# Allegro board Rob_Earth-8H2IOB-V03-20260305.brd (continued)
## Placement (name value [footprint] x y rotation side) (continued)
TVS3616  ESD54231N-2/TR  [ESD0402H0_55-ESD54231]  186.1 7.96 270 top
TVS3617  ESD54231N-2/TR  [ESD0402H0_55-ESD54231]  188.64 7.94 270 top
TVS3900  ESD54231N-2/TR  [ESD0402H0_55-ESD54231]  128.54 111.52 270 top
TVS3901  ESD54231N-2/TR  [ESD0402H0_55-ESD54231]  128.54 109.57 90 top
U500  LM5143QRWGRQ1  [QFN40-0_5-6X6H0_8-LM5143]  91.51 72.71 270 bottom
U501  LM5060Q1MM/NOPB  [VSSOP10-0_5-3X5H1_1-IM5060]  130.12 15.27 90 bottom
U504  74LVC1T45XC6G/TR  [SC70-6-0_65-2X1_25H1_1]  127.98 22.21 270 bottom
U506  SGM431VAXN3LG/TR  [SOT23H1_2]  123.05 14.07 270 bottom
U600  MAX25207ATPA/VY+  [QFN20-0_5-4X4H0_8]  69.79 54.01 90 bottom
U700  LM5177DCPR  [TSSOP38-0_5-9_8X4_5H1_2]  102.13 29.95 180 bottom
U800  SGM6613AYTQX13GTR  [QFN13-0_5-3X3_5H0_8-SGM6613A]  120.96 6.37 270 bottom
U802  SGM61030BXTEP7G/TR  [DFN7-0_5-SQ2H0_8-SGM61030]  54.9 40.69 90 bottom
U804  SGM2590DXN5G/TR  [SOT23-5H1_45]  50.91 57.1 90 bottom
U805  SGM2590DXN5G/TR  [SOT23-5H1_45]  50.93 52.47 90 bottom
U806  SGM61030BXTEP7G/TR  [DFN7-0_5-SQ2H0_8-SGM61030]  55.39 112.4 180 bottom
U807  SGM61030BXTEP7G/TR  [DFN7-0_5-SQ2H0_8-SGM61030]  139.54 89.39 0 top
U808  SGM2590DXN5G/TR  [SOT23-5H1_45]  139.48 94.14 180 top
U900  IT6563FN/DW(EW1)  [QFN56-0_4-7X7H0_9-IT6563]  36.3 20.31 90 bottom
U902  74LVC1G07XC5G/TR  [SC70-5H1_1]  30.21 29.79 180 bottom
U1000  IT6563FN/DW(EW1)  [QFN56-0_4-7X7H0_9-IT6563]  55.35 30.07 270 bottom
U1001  74LVC1G07XC5G/TR  [SC70-5H1_1]  61.05 20.05 90 bottom
U1100  IT6563FN/DW(EW1)  [QFN56-0_4-7X7H0_9-IT6563]  40.08 40.62 270 bottom
U1101  74LVC1G07XC5G/TR  [SC70-5H1_1]  50.91 46.2 90 bottom
U1400  HX5084NL  [SOP24-0_99-15_24X7_62H4_14]  117.53 102.02 180 top
U1401  RTL8211FSI-CG  [QFN48-0_4-SQ6_0H1_0]  99.41 107.39 180 top
U1500  RTL8111H  [QFN32-0_4-4X4H0_9-RTL8111H]  33 109.72 0 top
U1501  SGM2590DXN5G/TR  [SOT23-5H1_45]  42.05 115.03 0 top
U1502  74LVC1G07XC5G/TR  [SC70-5H1_1]  45.44 106.63 270 top
U1600  SGM2590DXN5G/TR  [SOT23-5H1_45]  127.39 63.22 180 top
U1601  74LVC1G07XC5G/TR  [SC70-5H1_1]  137.89 77.55 180 top
U1602  74LVC1G07XC5G/TR  [SC70-5H1_1]  141.45 77.55 180 top
U1603  GD25WQ40EEIG  [USON8-0_5-3_0X2_0H0_55]  126.98 79.44 270 top
U1604  AW39112DNR  [DFN8-0_35-1_4X1H0_4-SGM4553]  130.81 62.83 180 top
U1605  SN74AVC2T245RSWR  [QFN10-0_4-1_45X1_85H0_55]  128.09 74.17 270 top
U1606  SN74AVC2T245RSWR  [QFN10-0_4-1_45X1_85H0_55]  130.45 80.91 270 top
U1700  NC AT24C08D-SSHM-B  [SOIC8-1_27-4_9X6_0H1_75]  161.05 49.24 180 top
U1701  RTL8367S-CG  [QFP128-0_4-14X14H1_6-RTL8367S]  151.07 64.48 270 top
U1800  74LVC1G07XC5G/TR  [SC70-5H1_1]  144.65 78.77 270 top
U1801  SGM2036S-ADJXN5G/TR  [SOT23-5H1_25]  128.65 52.37 0 top
U1802  LP5810DYBHR  [BGA9-0_4-SQ1_43H0_4-LP5810]  135.99 27.59 270 top
U2300  SGM2566CGTDE8G/TR  [DFN8-0_5-2X2H0_8-SGM2566CG]  126.1 37.47 180 top
U2301  AW39112DNR  [DFN8-0_35-1_4X1H0_4-SGM4553]  131.14 47.2 0 top
U2302  74LVC1T45XC6G/TR  [SC70-6-0_65-2X1_25H1_1]  128.12 46.43 0 top
U2400  VL822-Q7  [QFN76-0_4-9X9H0_9-VL822-Q7]  155.21 89.68 180 top
U2401  GD25WQ40EEIG  [USON8-0_5-3_0X2_0H0_55]  160.97 78.93 0 top
U2500  SGM2590DXN5G/TR  [SOT23-5H1_45]  122.84 53.91 180 bottom
U2501  SY6288F1ABC  [SOT23-6H1_4]  137.82 75.87 0 bottom
U2502  SY6288F1ABC  [SOT23-6H1_4]  133.37 75.92 0 bottom
U2503  CH334H  [QFN28-0_5-5X5H0_8]  134.95 52.41 270 bottom
U2504  SY6288F1ABC  [SOT23-6H1_4]  137.67 65.47 0 bottom
U2505  SY6288F1ABC  [SOT23-6H1_4]  133.17 65.47 0 bottom
U2700  SY6288F1ABC  [SOT23-6H1_4]  140.83 105.27 0 top
U2701  SY6288F1ABC  [SOT23-6H1_4]  163.33 118.34 270 top
U2702  SY6288F1ABC  [SOT23-6H1_4]  149.1 111.33 270 top
U2703  SY6288F1ABC  [SOT23-6H1_4]  149.39 105.44 180 top
U2800  TAS5805MPWP  [TSSOP28-0_65-9_7X4_4H1_2-TAS5805M]  81.63 101.76 90 bottom
U2803  DS1308U-18+T  [USOP8-0_65-H1_1-DS1308]  102.97 18.74 0 bottom
U2805  NC 74LVC1G07XC5G/TR  [SC70-5H1_1]  73.6 97 90 bottom
U2900  MAX96712GTB/V+T  [QFN64-0_5-9X9H0_8-MAX96712]  42.09 95.93 45 bottom
U3000  MAX96712GTB/V+T  [QFN64-0_5-9X9H0_8-MAX96712]  39.48 69.53 45 bottom
U3002  SY6897ATLC  [QFN12-0_45-2X2H0_6-SY6897A]  26.22 75.79 180 top
U3100  SY6897ATLC  [QFN12-0_45-2X2H0_6-SY6897A]  28.72 98.83 90 top
U3101  SY6897ATLC  [QFN12-0_45-2X2H0_6-SY6897A]  26.19 92.67 180 top
U3102  SY6897ATLC  [QFN12-0_45-2X2H0_6-SY6897A]  26.21 86.99 180 top
U3103  SY6897ATLC  [QFN12-0_45-2X2H0_6-SY6897A]  26.23 81.38 180 top
U3104  TCA6424ARGJR  [QF32-0_5-5X5H0_6]  33.32 54.38 180 bottom
U3200  SGM61030BXTEP7G/TR  [DFN7-0_5-SQ2H0_8-SGM61030]  54.23 62.87 90 bottom
U3201  SGM2566CGTDE8G/TR  [DFN8-0_5-2X2H0_8-SGM2566CG]  46.85 105.52 270 bottom
U3202  SGM2036S-1.2XN5G/TR  [SOT23-5H1_25]  55.67 102.62 0 bottom
U3203  SY6897ATLC  [QFN12-0_45-2X2H0_6-SY6897A]  26.19 69.56 180 top
U3204  SY6897ATLC  [QFN12-0_45-2X2H0_6-SY6897A]  26.22 63.69 180 top
U3205  SY6897ATLC  [QFN12-0_45-2X2H0_6-SY6897A]  26.22 56.97 180 top
U3400  E  [DFN8-0_65-3X3H1]  133.13 110.99 180 bottom
U3402  MCP2562FDT-E/MF  [DFN8-0_65-3X3H1]  124.93 110.98 180 bottom
U3404  MCP2562FDT-E/MF  [DFN8-0_65-3X3H1]  117.36 110.99 180 bottom
U3405  MCP2562FDT-E/MF  [DFN8-0_65-3X3H1]  110.13 110.98 180 bottom
U3406  SN74AVC2T245RSWR  [QFN10-0_4-1_45X1_85H0_55]  133.11 97.46 0 bottom
U3407  MCP2518FDT-E/QBB  [VDFN14-0_65-4_5X3H0_9]  138.55 102.7 0 bottom
U3408  SN74AVC2T245RSWR  [QFN10-0_4-1_45X1_85H0_55]  111.26 90.69 270 bottom
U3409  MCP2518FDT-E/QBB  [VDFN14-0_65-4_5X3H0_9]  127.9 102.7 0 bottom
U3410  SN74AVC2T245RSWR  [QFN10-0_4-1_45X1_85H0_55]  127.21 97.53 0 bottom
U3411  MCP2518FDT-E/QBB  [VDFN14-0_65-4_5X3H0_9]  108.7 95.7 0 bottom
U3412  AW39204QNR  [QFN12-0_4-1_8X1_8H0_6-SGM4574]  133.38 92.51 180 bottom
U3413  MCP2518FDT-E/QBB  [VDFN14-0_65-4_5X3H0_9]  108.75 104 0 bottom
U3414  AW39204QNR  [QFN12-0_4-1_8X1_8H0_6-SGM4574]  127.02 92.68 180 bottom
U3500  TLV320ADC3140IRTWR  [QFN24-0_5-4X4H0_8-TLV320ADC3140]  91 95.15 180 top
U3501  TLV320ADC3140IRTWR  [QFN24-0_5-4X4H0_8-TLV320ADC3140]  51.6 112.12 270 top
U3606  SGM4551YN8G/TR  [SOT23-8H1_45]  127.94 8.64 90 top
U3607  EMC2303-1-KP-TR  [QFN12-0_8-SQ4_0H0_9]  133.85 13 90 top
U3901  SIT3088EESA  [SO8-1_27-4_9X3_9H1_7-SIT3088]  134.79 110.56 180 top
U4000  SIT3232EEUE  [TSSOP16-0_65-5X4_4H1_2]  139.4 117.86 180 top
U4001  SN74AVC2T245RSWR  [QFN10-0_4-1_45X1_85H0_55]  135.19 105.17 180 top
U4002  SN74AVC2T245RSWR  [QFN10-0_4-1_45X1_85H0_55]  129.43 105.17 180 top
U4003  74LVC1G07XC5G/TR  [SC70-5H1_1]  142.1 112.22 180 top
Y900  27MHz  [CRY4-2016]  42.62 26.15 90 bottom
Y1000  27MHz  [CRY4-2016]  48.99 24.28 270 bottom
Y1100  27MHz  [CRY4-2016]  33.9 34.85 270 bottom
Y1400  25MHz  [CRY4-2016H0_5-8Y24000046]  101.58 99.93 0 top
Y1500  25MHz  [CRY4-2016H0_5-8Y24000046]  33.1 116.57 180 top
Y1700  25MHz  [CRY4-2016H0_5-8Y24000046]  151.29 51.86 0 top
Y2300  40MHz  [CRY4-2016H0_5]  109.5 100.08 180 bottom
Y2400  25MHz  [CRY4-2016H0_5-8Y24000046]  144.9 92.03 270 top
Y2500  12MHz  [CRY4_3225]  135.08 44.63 180 bottom
Y2800  32.768KHz  [CRY2-3215]  97.19 16.93 270 bottom
Y2900  NC 25MHz  [CRY4-2016H0_5-8Y24000046]  31.35 99.32 225 bottom
Y2901  25MHz  [OSC4-2520H0_9]  31.03 94.19 135 bottom
Y3000  NC 25MHz  [CRY4-2016H0_5-8Y24000046]  28.74 72.91 225 bottom
Y3400  40MHz  [CRY4-2016H0_5]  139.83 107.32 180 bottom
Y3401  40MHz  [CRY4-2016H0_5]  128.65 108.25 180 bottom
Y3402  40MHz  [CRY4-2016H0_5]  114.7 107.05 90 bottom

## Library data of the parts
B900-B903 B1000-B1003 B1100-B1103 B1700-B1706 B2500 B2900 B2901 B2903 B3000 B3002 B3003 B3500-B3505 B3600 B3602 = L_Bead
B2400-B2402 B2902 B3001 = L_BEAD
C500-C551 C608-C623 C700-C713 C800-C815 C820-C838 C840 C900-C928 C1000-C1028 C1102-C1128 C1400-C1423 C1500-C1504 C1506-C1521 C1600-C1613 C1700-C1755 C1800-C1803 C1808 C1900 C1901 C2000 C2001 C2300-C2309 C2313-C2315 C2399-C2434 C2500-C2503 C2505-C2509 C2511-C2513 C2515-C2519 C2521 C2522 C2696-C2701 C2703 C2705-C2708 C2711 C2800-C2831 C2838 C2900-C2942 C3000-C3040 C3044 C3045 C3049 C3100-C3113 C3200-C3210 C3221 C3229-C3238 C3400 C3401 C3404 C3405 C3407 C3408 C3411 C3412 C3414-C3417 C3419-C3422 C3424-C3439 C3498-C3536 C3623-C3628 C3903 C4000-C4009 = CAP
C1100 C1101 = CAP: signal model: CAP_0201_DISCRETE_100NF/10V_1_100nF/10V_1
C3406 C3413 C3418 C3423 R514 R516 = RES_PAD
CM2000-CM2003 CM2701 CM2705 CM2708 CM2710 = L_CC_MCF12102G900-T
CM3400-CM3403 = L_CC_ACT45B-101-2P-TL003
CMC1200-CMC1207 CMC1300-CMC1303 CMC2700 CMC2702-CMC2704 CMC2706 CMC2707 CMC2709 CMC2711 = L_CC_NFG0QHB542HS2D
CN2300 = CON_PCIE-M_75P_51743-0750C-012
CON2900 CON3000 = CON_4P_A-M4008T-4
CR1200 CR1201 CR1207 CR1208 CR1300 CR1301 CR1500 CR1501 CR1900-CR1907 CR2000-CR2003 CR2300 CR2304 CR2305 CR2307 CR2308 = DIODE_TVS_PESDALC10N5VU
CT501 = CAP_VZT471
CT700 CT701 CT1900-CT1903 CT2500-CT2503 CT2700 CT2701 = CAP_T
D500 D501 D505 D507 D2900-D2903 D3000-D3003 D4000 D4001 TVS1202-TVS1206 TVS1209-TVS1213 TVS1302-TVS1306 TVS1500-TVS1502 TVS1800-TVS1810 TVS1900-TVS1904 TVS1906-TVS1917 TVS2000-TVS2013 TVS2301-TVS2303 TVS2306 TVS2309 TVS2500-TVS2507 TVS3400-TVS3403 TVS3500-TVS3507 TVS3614-TVS3617 TVS3900 TVS3901 = DIODE_TVS
D502-D504 D506 D508 D509 D600 D1600 D1700 D1800 D2400 D3600 D3601 = DIODE_SCHOTTKY_D
D900 D1100 D1200 = DIODE_SCHOTTKY
D2800-D2803 = DIODE_TVS_WS30DF
D3400-D3403 = DIODE_TVS_AZ9424-02S_0
F500 F501 = FUSE
HOLE3600-HOLE3611 M3602 M3603 M3605 M3606 TP500-TP502 TP602 TP603 TP700 TP801 TP802 TP804-TP806 TP900-TP911 TP1000-TP1008 TP1100-TP1111 TP1200-TP1206 TP1300 TP1301 TP1400-TP1404 TP1600 TP1700 TP1701 TP1800-TP1803 TP1808 TP2400-TP2414 TP2500-TP2502 TP2600 TP2601 TP2603-TP2605 TP2608-TP2610 TP2612-TP2620 TP2622 TP2623 TP2625-TP2632 TP2700-TP2702 TP2800 TP2804 TP3200 TP3201 TP3400-TP3407 TP3499-TP3513 = TP
J501 = CON_WAFER_4P_ABA-POW-003-K50
J1200 J1201 J1300 = CON_HDMI_19P_161655051
J1500 = CON_RJ45_10P_LB2016RJ10P
J1600 J3500 J3501 = CON_WTB_6P_JH125LF-06
J1900 J1901 J2000 J2001 = CON_RJ45_LB-US3RJ01-02
J2600 = CON_BTB_240P_SEAF_40_060
J2700 = CON_BTB_200P_SEAM-20-060
J2800 = CON_BATTERY_2P_BS-08
J2801 J2802 = CON_WTB_2P_JH2501LF-2A
J3301 J3302 J3304 J3305 = CON_WTB_JH125LF-02
J3303 = CON_WTB_3P_JH125LF-03_0
J3310 = CON_WTB_5P_JH200AWF-5A
J3400 = CON_HR_20P_BRA-ST-20102001S-2.8
J3600 J3601 = CON_WTB_4P_JH125WF-04_0
JP502-JP505 JP600 JP601 = Short_L1
JP900-JP909 JP1000-JP1009 JP1100-JP1109 = Short_L5
L500-L503 L600 L800-L803 L1400 L1700 L2800-L2803 L2900-L2907 L3000-L3007 L3200 = L_PI
L700 = L_PI_SL-11_9X11H10_0_DISCRETE_4.7UH/25.4A
LED500 LED1700 LED3101 = DIODE_LED_S
NUT2301 = NUT_1
Q501-Q506 Q600 Q601 Q700-Q703 = MOSFET_N_WMQ048NV6LG2
Q507 = TRANSISTOR_NPN_T
Q1400 Q3101 = MOSFET_N_ESD
R500-R513 R515 R517-R544 R600-R614 R700-R714 R800-R806 R808 R810-R813 R815-R821 R896 R898-R901 R903 R905 R906 R908 R910 R911 R913-R915 R917 R918 R920 R922-R934 R1000-R1016 R1018-R1032 R1100-R1134 R1200-R1202 R1209-R1212 R1214-R1217 R1226-R1229 R1231-R1233 R1297-R1300 R1309-R1312 R1314-R1316 R1400-R1436 R1500-R1523 R1600-R1620 R1700 R1701 R1703-R1715 R1719 R1722 R1800-R1806 R1809-R1814 R1900-R1913 R2000-R2007 R2009-R2013 R2015 R2300-R2303 R2307-R2309 R2399-R2420 R2500-R2521 R2700 R2701 R2703-R2717 R2719-R2721 R2724 R2725 R2728 R2734 R2736-R2738 R2740-R2749 R2800-R2813 R2816-R2818 R2820 R2901 R2902 R2904 R2905 R2907 R2908 R2910-R2932 R3001 R3002 R3004-R3008 R3010-R3021 R3023-R3033 R3100-R3116 R3118 R3200-R3205 R3208 R3221-R3229 R3300-R3303 R3401-R3422 R3425 R3426 R3496-R3537 R3606 R3608 R3622-R3624 R3627-R3631 R3633-R3636 R3901 R3903 R3909 R3910 R3915 R4000-R4010 = RES
R902 R904 R907 R909 R912 R916 R919 R921 = RES: signal model: RES_0201_DISCRETE_5.1_1_5.1_1
R1017 = RES: signal model: RES_0201_DISCRETE_5_1_1_5_1_1
R1702 = RES: signal model: DEFAULT_RESISTOR_0.001OHM_1_2
R1716-R1718 R1720 R1721 = RES: signal model: DEFAULT_RESISTOR_2490OHM_1_2
R2718 = RES: signal model: RES_0201_DISCRETE_NC_0_1_NC_0_1
R2900 R2903 R2906 R2909 R3000 R3003 R3009 R3022 = L_FI
RT2300 RT2400 = R_THERMISTOR
SW500 = CON_SW_4P_TSK-051510-160-KJ
SW501 = CON_SW_4P_DHN_02_V-TR
SW3300 = CON_SW_12P_WDHP-06-TSGER
U500 = IC_LM5143
U501 = IC_LM5060Q1MM_6
U504 U2302 = IC_4: room: NO_ROOM
U506 = IC_GM431VAXN3LG/TR
U600 = IC_MAX25207
U700 = IC_LM5177DCPR
U800 = IC_SGM6613AYTQX13G/TR_1
U802 U806 U807 U3200 = IC_SGM61030BXTEP7G
U804 U805 U808 U1501 U1600 U2500 = IC_SGM2590D
U900 U1000 U1100 = IC_IT6563FNDW_EW1_2
U902 U1001 U1101 U1800 U2805 U4003 = IC_2
U1400 = IC_HX5084NL
U1401 = IC_RTL8211FS
U1500 = RL5877_0
U1502 U1601 U1602 = IC_0
U1603 U2401 = IC_GD25Q40CEIG_0
U1604 U2301 = IC_SGM4553YXDO8G
U1605 U1606 U3406 U3408 U3410 U4001 U4002 = IC_SN74AVC2T245RSWR_1
U1700 = IC_AT24C08D
U1701 = IC_RTL8367S-CG_3
U1801 = IC_SGM2036-ADJYN5G
U1802 = IC_LP5810
U2300 U3201 = IC_SGM2566C
U2400 = IC_VL822_QFN-76_0
U2501 U2502 U2504 U2505 U2700-U2703 = IC_SY6288F1ABC
U2503 = IC_CH334H
U2800 = IC_TAS5805MPWP_4
U2803 = IC_DS1308
U2900 U3000 = IC_MAX96712_0
U3002 U3100-U3103 U3203-U3205 = IC_SY6897ATLC
U3104 = IC_TCA6424ARGJR
U3202 = IC_SGM2036S
U3400 U3402 U3404 U3405 = IC_MCP2562_0
U3407 U3409 U3411 U3413 = IC_MCP2518FDT-H_0
U3412 U3414 = IC_SGM4574YUQN12G
U3500 U3501 = IC_TLV320ADC3140IRTWR
U3606 = IC_SGM4551YN8G/TR
U3607 = IC_EMC2303-1-KP-TR_1
U3901 = IC_SIT3088EESA
U4000 = IC_SIT3232EEUE
Y900 Y1000 Y1100 Y1400 Y1500 Y1700 Y2300 Y2400 Y2500 Y2900 Y3000 Y3400-Y3402 = CRYSTAL
Y2800 = CRYSTAL_32.768K
Y2901 = OSC_2C26000004

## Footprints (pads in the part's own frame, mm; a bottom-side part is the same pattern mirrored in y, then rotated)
0201
  rect 0.28x0.3 smd: 1(-0.24,0) 2(0.24,0)
0402
  rect 0.45x0.5 smd: 1(-0.4,0) 2(0.4,0)
0402W
  rect 0.5x0.7 smd: 1(-0.425,0) 2(0.425,0)
1206_SP
  rect 1x1.6 smd: 1(-1.4,0)
  rect 2.85x1.6 smd: 2(0.475,0)
BAT2-25_2X20H5_3
  rect 3.5x3.8 smd: 1(13,0)
  rect 4.3x2.8 smd: 2(-8.8,0)
BGA9-0_4-SQ1_43H0_4-LP5810
  round 0.25 smd: A1(-0.4,0.4) A2(0,0.4) A3(0.4,0.4) B1(-0.4,0) B2(0,0) B3(0.4,0) C1(-0.4,-0.4) C2(0,-0.4) C3(0.4,-0.4)
BTB200F-1_27H6_05-SEAF-20
  round 1.27 hole 1.22 unplated: (-14.49,0) (14.49,-3.05)
  round 0.64 smd: A1(12.065,-5.715) A2(10.795,-5.715) A3(9.525,-5.715) A4(8.255,-5.715) A5(6.985,-5.715) A6(5.715,-5.715) A7(4.445,-5.715) A8(3.175,-5.715) A9(1.905,-5.715) A10(0.635,-5.715) A11(-0.635,-5.715) A12(-1.905,-5.715) A13(-3.175,-5.715) A14(-4.445,-5.715) A15(-5.715,-5.715) A16(-6.985,-5.715) A17(-8.255,-5.715) A18(-9.525,-5.715) A19(-10.795,-5.715) A20(-12.065,-5.715) B1(12.065,-4.445) B2(10.795,-4.445) B3(9.525,-4.445) B4(8.255,-4.445) B5(6.985,-4.445) B6(5.715,-4.445) B7(4.445,-4.445) B8(3.175,-4.445) B9(1.905,-4.445) B10(0.635,-4.445) B11(-0.635,-4.445) B12(-1.905,-4.445) B13(-3.175,-4.445) B14(-4.445,-4.445) B15(-5.715,-4.445) B16(-6.985,-4.445) B17(-8.255,-4.445) B18(-9.525,-4.445) B19(-10.795,-4.445) B20(-12.065,-4.445) C1(12.065,-3.175) C2(10.795,-3.175) C3(9.525,-3.175) C4(8.255,-3.175) C5(6.985,-3.175) C6(5.715,-3.175) C7(4.445,-3.175) C8(3.175,-3.175) C9(1.905,-3.175) C10(0.635,-3.175) C11(-0.635,-3.175) C12(-1.905,-3.175) C13(-3.175,-3.175) C14(-4.445,-3.175) C15(-5.715,-3.175) C16(-6.985,-3.175) C17(-8.255,-3.175) C18(-9.525,-3.175) C19(-10.795,-3.175) C20(-12.065,-3.175) D1(12.065,-1.905) D2(10.795,-1.905) D3(9.525,-1.905) D4(8.255,-1.905) D5(6.985,-1.905) D6(5.715,-1.905) D7(4.445,-1.905) D8(3.175,-1.905) D9(1.905,-1.905) D10(0.635,-1.905) D11(-0.635,-1.905) D12(-1.905,-1.905) D13(-3.175,-1.905) D14(-4.445,-1.905) D15(-5.715,-1.905) D16(-6.985,-1.905) D17(-8.255,-1.905) D18(-9.525,-1.905) D19(-10.795,-1.905) D20(-12.065,-1.905) E1(12.065,-0.635) E2(10.795,-0.635) E3(9.525,-0.635) E4(8.255,-0.635) E5(6.985,-0.635) E6(5.715,-0.635) E7(4.445,-0.635) E8(3.175,-0.635) E9(1.905,-0.635) E10(0.635,-0.635) E11(-0.635,-0.635) E12(-1.905,-0.635) E13(-3.175,-0.635) E14(-4.445,-0.635) E15(-5.715,-0.635) E16(-6.985,-0.635) E17(-8.255,-0.635) E18(-9.525,-0.635) E19(-10.795,-0.635) E20(-12.065,-0.635) F1(12.065,0.635) F2(10.795,0.635) F3(9.525,0.635) F4(8.255,0.635) F5(6.985,0.635) F6(5.715,0.635) F7(4.445,0.635) F8(3.175,0.635) F9(1.905,0.635) F10(0.635,0.635) F11(-0.635,0.635) F12(-1.905,0.635) F13(-3.175,0.635) F14(-4.445,0.635) F15(-5.715,0.635) F16(-6.985,0.635) F17(-8.255,0.635) F18(-9.525,0.635) F19(-10.795,0.635) F20(-12.065,0.635) G1(12.065,1.905) G2(10.795,1.905) G3(9.525,1.905) G4(8.255,1.905) G5(6.985,1.905) G6(5.715,1.905) G7(4.445,1.905) G8(3.175,1.905) G9(1.905,1.905) G10(0.635,1.905) G11(-0.635,1.905) G12(-1.905,1.905) G13(-3.175,1.905) G14(-4.445,1.905) G15(-5.715,1.905) G16(-6.985,1.905) G17(-8.255,1.905) G18(-9.525,1.905) G19(-10.795,1.905) G20(-12.065,1.905) H1(12.065,3.175) H2(10.795,3.175) H3(9.525,3.175) H4(8.255,3.175) H5(6.985,3.175) H6(5.715,3.175) H7(4.445,3.175) H8(3.175,3.175) H9(1.905,3.175) H10(0.635,3.175) H11(-0.635,3.175) H12(-1.905,3.175) H13(-3.175,3.175) H14(-4.445,3.175) H15(-5.715,3.175) H16(-6.985,3.175) H17(-8.255,3.175) H18(-9.525,3.175) H19(-10.795,3.175) H20(-12.065,3.175) I1(12.065,4.445) I2(10.795,4.445) I3(9.525,4.445) I4(8.255,4.445) I5(6.985,4.445) I6(5.715,4.445) I7(4.445,4.445) I8(3.175,4.445) I9(1.905,4.445) I10(0.635,4.445) I11(-0.635,4.445) I12(-1.905,4.445) I13(-3.175,4.445) I14(-4.445,4.445) I15(-5.715,4.445) I16(-6.985,4.445) I17(-8.255,4.445) I18(-9.525,4.445) I19(-10.795,4.445) I20(-12.065,4.445) J1(12.065,5.715) J2(10.795,5.715) J3(9.525,5.715) J4(8.255,5.715) J5(6.985,5.715) J6(5.715,5.715) J7(4.445,5.715) J8(3.175,5.715) J9(1.905,5.715) J10(0.635,5.715) J11(-0.635,5.715) J12(-1.905,5.715) J13(-3.175,5.715) J14(-4.445,5.715) J15(-5.715,5.715) J16(-6.985,5.715) J17(-8.255,5.715) J18(-9.525,5.715) J19(-10.795,5.715) J20(-12.065,5.715)
BTB240F-1_27H6_05-SEAF-40
  round 1.27 hole 1.22 unplated: (-27.19,0) (27.19,-3.05)
  round 0.64 smd: A1(24.765,-3.175) A2(23.495,-3.175) A3(22.225,-3.175) A4(20.955,-3.175) A5(19.685,-3.175) A6(18.415,-3.175) A7(17.145,-3.175) A8(15.875,-3.175) A9(14.605,-3.175) A10(13.335,-3.175) A11(12.065,-3.175) A12(10.795,-3.175) A13(9.525,-3.175) A14(8.255,-3.175) A15(6.985,-3.175) A16(5.715,-3.175) A17(4.445,-3.175) A18(3.175,-3.175) A19(1.905,-3.175) A20(0.635,-3.175) A21(-0.635,-3.175) A22(-1.905,-3.175) A23(-3.175,-3.175) A24(-4.445,-3.175) A25(-5.715,-3.175) A26(-6.985,-3.175) A27(-8.255,-3.175) A28(-9.525,-3.175) A29(-10.795,-3.175) A30(-12.065,-3.175) A31(-13.335,-3.175) A32(-14.605,-3.175) A33(-15.875,-3.175) A34(-17.145,-3.175) A35(-18.415,-3.175) A36(-19.685,-3.175) A37(-20.955,-3.175) A38(-22.225,-3.175) A39(-23.495,-3.175) A40(-24.765,-3.175) B1(24.765,-1.905) B2(23.495,-1.905) B3(22.225,-1.905) B4(20.955,-1.905) B5(19.685,-1.905) B6(18.415,-1.905) B7(17.145,-1.905) B8(15.875,-1.905) B9(14.605,-1.905) B10(13.335,-1.905) B11(12.065,-1.905) B12(10.795,-1.905) B13(9.525,-1.905) B14(8.255,-1.905) B15(6.985,-1.905) B16(5.715,-1.905) B17(4.445,-1.905) B18(3.175,-1.905) B19(1.905,-1.905) B20(0.635,-1.905) B21(-0.635,-1.905) B22(-1.905,-1.905) B23(-3.175,-1.905) B24(-4.445,-1.905) B25(-5.715,-1.905) B26(-6.985,-1.905) B27(-8.255,-1.905) B28(-9.525,-1.905) B29(-10.795,-1.905) B30(-12.065,-1.905) B31(-13.335,-1.905) B32(-14.605,-1.905) B33(-15.875,-1.905) B34(-17.145,-1.905) B35(-18.415,-1.905) B36(-19.685,-1.905) B37(-20.955,-1.905) B38(-22.225,-1.905) B39(-23.495,-1.905) B40(-24.765,-1.905) C1(24.765,-0.635) C2(23.495,-0.635) C3(22.225,-0.635) C4(20.955,-0.635) C5(19.685,-0.635) C6(18.415,-0.635) C7(17.145,-0.635) C8(15.875,-0.635) C9(14.605,-0.635) C10(13.335,-0.635) C11(12.065,-0.635) C12(10.795,-0.635) C13(9.525,-0.635) C14(8.255,-0.635) C15(6.985,-0.635) C16(5.715,-0.635) C17(4.445,-0.635) C18(3.175,-0.635) C19(1.905,-0.635) C20(0.635,-0.635) C21(-0.635,-0.635) C22(-1.905,-0.635) C23(-3.175,-0.635) C24(-4.445,-0.635) C25(-5.715,-0.635) C26(-6.985,-0.635) C27(-8.255,-0.635) C28(-9.525,-0.635) C29(-10.795,-0.635) C30(-12.065,-0.635) C31(-13.335,-0.635) C32(-14.605,-0.635) C33(-15.875,-0.635) C34(-17.145,-0.635) C35(-18.415,-0.635) C36(-19.685,-0.635) C37(-20.955,-0.635) C38(-22.225,-0.635) C39(-23.495,-0.635) C40(-24.765,-0.635) D1(24.765,0.635) D2(23.495,0.635) D3(22.225,0.635) D4(20.955,0.635) D5(19.685,0.635) D6(18.415,0.635) D7(17.145,0.635) D8(15.875,0.635) D9(14.605,0.635) D10(13.335,0.635) D11(12.065,0.635) D12(10.795,0.635) D13(9.525,0.635) D14(8.255,0.635) D15(6.985,0.635) D16(5.715,0.635) D17(4.445,0.635) D18(3.175,0.635) D19(1.905,0.635) D20(0.635,0.635) D21(-0.635,0.635) D22(-1.905,0.635) D23(-3.175,0.635) D24(-4.445,0.635) D25(-5.715,0.635) D26(-6.985,0.635) D27(-8.255,0.635) D28(-9.525,0.635) D29(-10.795,0.635) D30(-12.065,0.635) D31(-13.335,0.635) D32(-14.605,0.635) D33(-15.875,0.635) D34(-17.145,0.635) D35(-18.415,0.635) D36(-19.685,0.635) D37(-20.955,0.635) D38(-22.225,0.635) D39(-23.495,0.635) D40(-24.765,0.635) E1(24.765,1.905) E2(23.495,1.905) E3(22.225,1.905) E4(20.955,1.905) E5(19.685,1.905) E6(18.415,1.905) E7(17.145,1.905) E8(15.875,1.905) E9(14.605,1.905) E10(13.335,1.905) E11(12.065,1.905) E12(10.795,1.905) E13(9.525,1.905) E14(8.255,1.905) E15(6.985,1.905) E16(5.715,1.905) E17(4.445,1.905) E18(3.175,1.905) E19(1.905,1.905) E20(0.635,1.905) E21(-0.635,1.905) E22(-1.905,1.905) E23(-3.175,1.905) E24(-4.445,1.905) E25(-5.715,1.905) E26(-6.985,1.905) E27(-8.255,1.905) E28(-9.525,1.905) E29(-10.795,1.905) E30(-12.065,1.905) E31(-13.335,1.905) E32(-14.605,1.905) E33(-15.875,1.905) E34(-17.145,1.905) E35(-18.415,1.905) E36(-19.685,1.905) E37(-20.955,1.905) E38(-22.225,1.905) E39(-23.495,1.905) E40(-24.765,1.905) F1(24.765,3.175) F2(23.495,3.175) F3(22.225,3.175) F4(20.955,3.175) F5(19.685,3.175) F6(18.415,3.175) F7(17.145,3.175) F8(15.875,3.175) F9(14.605,3.175) F10(13.335,3.175) F11(12.065,3.175) F12(10.795,3.175) F13(9.525,3.175) F14(8.255,3.175) F15(6.985,3.175) F16(5.715,3.175) F17(4.445,3.175) F18(3.175,3.175) F19(1.905,3.175) F20(0.635,3.175) F21(-0.635,3.175) F22(-1.905,3.175) F23(-3.175,3.175) F24(-4.445,3.175) F25(-5.715,3.175) F26(-6.985,3.175) F27(-8.255,3.175) F28(-9.525,3.175) F29(-10.795,3.175) F30(-12.065,3.175) F31(-13.335,3.175) F32(-14.605,3.175) F33(-15.875,3.175) F34(-17.145,3.175) F35(-18.415,3.175) F36(-19.685,3.175) F37(-20.955,3.175) F38(-22.225,3.175) F39(-23.495,3.175) F40(-24.765,3.175)
CMC4-0_4-0_65X0_5H0_35
  rect 0.2x0.3 smd: 1(-0.2,-0.25) 2(0.2,-0.25) 3(0.2,0.25) 4(-0.2,0.25)
CMC4-0_65X0_5H0_3
  rect 0.25x0.23 smd: 1(-0.225,0.24) 2(0.225,0.24) 3(0.225,-0.24) 4(-0.225,-0.24)
CON4-12X24_3H14_4-M4008T-4
  round 1 hole 0.65: 1(-2,2) 2(-2,-2) 3(2,2) 4(2,-2)
  round 2 hole 1.5: 5(-3.2,4.35) 6(3.2,4.35) 7(-3.2,-4.35) 8(3.2,-4.35)
  rect 4x1 smd: G1(0,4.65)
  rect 3.6x1 smd: G2(0,-4.65)
  custom 1.8x1.8 smd: G3(0,0)
CON30-H31-LB-US3RJ02-01
  round 1.4 hole 1: 1(5.715,13.43) 2(4.445,15.97) 3(3.175,13.43) 4(1.905,15.97) 5(0.635,13.43) 6(-0.635,15.97) 7(-1.905,13.43) 8(-3.175,15.97) 9(-4.445,13.43) 10(-5.715,15.97) D1(-7.205,18.81) D2(-4.665,18.81) D3(4.665,18.81) D4(7.205,18.81) U1(-3.5,4.63) U2(-1,4.63) U3(1,4.63) U4(3.5,4.63) U5(4,6.13) U6(2,6.13) U7(0,6.13) U8(-2,6.13) U9(-4,6.13) U10(-3.5,7.83) U11(-1,7.83) U12(1,7.83) U13(3.5,7.83) U14(4,9.33) U15(2,9.33) U16(0,9.33) U17(-2,9.33) U18(-4,9.33)
  round 3.4 hole 2.8: G1(-6.57,8.31) G2(6.57,8.31) G3(6.57,2.63) G4(-6.57,2.63)
  oval 1.6x2.9 hole 1x2.3: G5(-9.325,11.6) G6(9.325,13.34) G7(9.325,0) G8(-9.325,0)
CRY2-3215
  rect 1x1.8 smd: 1(-1.25,0) 2(1.25,0)
CRY4-2016
  rect 0.9x0.8 smd: 1(-0.7,-0.55) 2(0.7,-0.55) 3(0.7,0.55) 4(-0.7,0.55)
CRY4-2016H0_5
  rect 0.9x0.8 smd: 1(-0.7,-0.55) 2(0.7,-0.55) 3(0.7,0.55) 4(-0.7,0.55)
CRY4-2016H0_5-8Y24000046
  rect 0.9x0.8 smd: 1(-0.7,-0.55) 2(0.7,-0.55) 3(0.7,0.55) 4(-0.7,0.55)
CRY4_3225
  rect 1.4x1.2 smd: 1(-1.1,-0.9) 2(1.1,-0.9) 3(1.1,0.9) 4(-1.1,0.9)
DFN7-0_5-SQ2H0_8-SGM61030
  rect 0.6x0.25 smd: 1(-0.9,0.75) 2(-0.9,0.25) 3(-0.9,-0.25) 4(-0.9,-0.75)
  rect 1.5x0.3 smd: 5(0.45,-0.6) 6(0.45,0) 7(0.45,0.6)
DFN8-0_5-2X2H0_8-SGM2566CG
  rect 0.25x0.5 smd: 1(-0.75,-0.95) 2(-0.25,-0.95) 3(0.25,-0.95) 4(0.75,-0.95) 5(0.75,0.95) 6(0.25,0.95) 7(-0.25,0.95) 8(-0.75,0.95)
  rect 1.6x0.9 smd: 9(0,0)
DFN8-0_35-1_4X1H0_4-SGM4553
  rect 0.18x0.5 smd: 1(-0.525,-0.35)
  rect 0.18x0.4 smd: 2(-0.175,-0.4) 3(0.175,-0.4) 4(0.525,-0.4) 5(0.525,0.4) 6(0.175,0.4) 7(-0.175,0.4) 8(-0.525,0.4)
DFN8-0_65-3X3H1
  rect 0.356x0.66 smd: 1(-0.975,-1.55) 2(-0.325,-1.55) 3(0.325,-1.55) 4(0.975,-1.55) 5(0.975,1.55) 6(0.325,1.55) 7(-0.325,1.55) 8(-0.975,1.55)
  rect 2.413x1.549 smd: 9(0,0)
DFN10-0_5-2_5X1H0_55
  rect 0.2x0.6 smd: 1(-1,-0.4) 2(-0.5,-0.4) 4(0.5,-0.4) 5(1,-0.4) 6(1,0.4) 7(0.5,0.4) 9(-0.5,0.4) 10(-1,0.4)
  rect 0.4x0.6 smd: 3(0,-0.4) 8(0,0.4)
DFN0603-2L-H0_34
  rect 0.22x0.32 smd: 1(-0.21,0) 2(0.21,0)
DFN1006-2-0_6X1_0H0_5
  rect 0.4x0.6 smd: 1(-0.35,0) 2(0.35,0)
DFN1006-2-H0_55
  rect 0.4x0.6 smd: 1(-0.35,0) 2(0.35,0)
DFN1006-2L-H0_5
  rect 0.4x0.6 smd: 1(-0.35,0) 2(0.35,0)
DFN1006-3-H0_55
  rect 0.4x0.25 smd: 1(-0.35,0.225) 2(-0.35,-0.225)
  rect 0.4x0.7 smd: 3(0.35,0)
DFN3333-8-H0_8
  rect 0.42x0.7 smd: 1(-0.975,-1.4) 2(-0.325,-1.4) 3(0.325,-1.4) 4(0.975,-1.4) 5(0.975,1.4) 6(0.325,1.4) 7(-0.325,1.4)
  custom 0.537x0.537 smd: 8(0,0.675)
DO-214AB-H2_82-SMCJ12CA
  rect 1.72x3.2 smd: 1(-3.205,0) 2(3.205,0)
DSW4-1_27H1_5-DHN-02
  rect 0.76x1.27 smd: 1(-0.635,-3.08) 2(0.635,-3.08) 3(0.635,3.08) 4(-0.635,3.08)
EMC4_4_5X3_2H3
  rect 1.35x0.9 smd: 1(-2.275,1.25) 2(-2.275,-1.25) 3(2.275,-1.25) 4(2.275,1.25)
ESD0402H0_35-RSES12V020R2
  rect 0.4x0.6 smd: 1(-0.52,0) 2(0.52,0)
ESD0402H0_55-ESD54231
  rect 0.4x0.55 smd: 1(-0.4,0) 2(0.4,0)
FB0402H0_5
  rect 0.5x0.5 smd: 1(-0.45,0) 2(0.45,0)
FB0603H0_95
  rect 0.6x0.8 smd: 1(-0.7,0) 2(0.7,0)
FUSE-3_2X1_63H1_0
  rect 1x1.8 smd: 1(-1.25,0) 2(1.25,0)
HD2X2-H10-123-39-30-1040
  round 3 hole 3 unplated: (0,-10.05)
  round 2.3 hole 1.8: 1(2.1,-2.75) 2(-2.1,-2.75) 3(2.1,2.75) 4(-2.1,2.75)
HD4X1-2_54H10-47053-1000
  round 1.25 hole 1.25 unplated: (-1.27,-2.16)
  round 1.6 hole 1.02: 1(3.81,0) 2(1.27,0) 3(-1.27,0) 4(-3.81,0)
HDMI19-H16_4-161655051
  round 1.7 hole 1.7 unplated: (-3.5,13.25) (0,0)
  round 0.8 hole 0.55: 1(-1,1.9) 2(-2,2.478) 3(-1,3.055) 4(-2,3.632) 5(-1,4.21) 6(-2,4.787) 7(-1,5.365) 8(-2,5.942) 9(-1,6.52) 10(-2,7.098) 11(-1,7.675) 12(-2,8.252) 13(-1,8.83) 14(-2,9.408) 15(-1,9.985) 16(-2,10.562) 17(-1,11.14) 18(-2,11.717) 19(-1,12.295)
  oval 1.4x3.2 hole 0.9x2.7: G1(1.75,3.75) G2(-4.75,1.15) G3(-4.75,10.15) G4(1.75,13.25)
HDS2X10-2H6_8-123-BRA-ST
  rect 1.1x2.5 smd: 1(-9,-2.25) 2(-7,-2.25) 3(-5,-2.25) 4(-3,-2.25) 5(-1,-2.25) 6(1,-2.25) 7(3,-2.25) 8(5,-2.25) 9(7,-2.25) 10(9,-2.25) 11(9,2.25) 12(7,2.25) 13(5,2.25) 14(3,2.25) 15(1,2.25) 16(-1,2.25) 17(-3,2.25) 18(-5,2.25) 19(-7,2.25) 20(-9,2.25)
HOLE-C5_0D2_2
  round 5 hole 2.2: 1(0,0)
LED0603H0_4
  rect 0.7x0.8 smd: 1(-0.7,0) 2(0.7,0)
LED0603H0_8
  rect 0.7x0.8 smd: 1(-0.7,0) 2(0.7,0)
LED0603X2H0_35
  rect 0.7x0.8 smd: 1(-0.7,0) 2(0.7,0)
MARK
  round 1.016 smd: 1(0,0)
NUT-C5_2D2_8H3_1
  round 5.2 hole 2.8: 1(0,0)
OSC4-2520H0_9
  rect 1x0.95 smd: 1(-0.925,-0.775) 2(0.925,-0.775) 3(0.925,0.775) 4(-0.925,0.775)
PCI75-H4_9-APCIA178
  round 1.1 hole 1.1 unplated: (-10,-1.5)
  round 1.6 hole 1.6 unplated: (10,-1.5)
  rect 0.3x1.55 smd: 1(-9.25,3.775) 2(-9,-3.775) 3(-8.75,3.775) 4(-8.5,-3.775) 5(-8.25,3.775) 6(-8,-3.775) 7(-7.75,3.775) 8(-7.5,-3.775) 9(-7.25,3.775) 10(-7,-3.775) 11(-6.75,3.775) 12(-6.5,-3.775) 13(-6.25,3.775) 14(-6,-3.775) 15(-5.75,3.775) 16(-5.5,-3.775) 17(-5.25,3.775) 18(-5,-3.775) 19(-4.75,3.775) 20(-4.5,-3.775) 21(-4.25,3.775) 22(-4,-3.775) 23(-3.75,3.775) 24(-3.5,-3.775) 25(-3.25,3.775) 26(-3,-3.775) 27(-2.75,3.775) 28(-2.5,-3.775) 29(-2.25,3.775) 30(-2,-3.775) 31(-1.75,3.775) 32(-1.5,-3.775) 33(-1.25,3.775) 34(-1,-3.775) 35(-0.75,3.775) 36(-0.5,-3.775) 37(-0.25,3.775) 38(0,-3.775) 39(0.25,3.775) 40(0.5,-3.775) 41(0.75,3.775) 42(1,-3.775) 43(1.25,3.775) 44(1.5,-3.775) 45(1.75,3.775) 46(2,-3.775) 47(2.25,3.775) 48(2.5,-3.775) 49(2.75,3.775) 50(3,-3.775) 51(3.25,3.775) 52(3.5,-3.775) 53(3.75,3.775) 54(4,-3.775) 55(4.25,3.775) 56(4.5,-3.775) 57(4.75,3.775) 58(5,-3.775) 67(7.25,3.775) 68(7.5,-3.775) 69(7.75,3.775) 70(8,-3.775) 71(8.25,3.775) 72(8.5,-3.775) 73(8.75,3.775) 74(9,-3.775) 75(9.25,3.775)
  rect 1.2x2.75 smd: G1(-10.35,3) G2(10.35,3)
QF32-0_5-5X5H0_6
  rect 0.28x0.7 smd: 1(-1.75,-2.405) 2(-1.25,-2.405) 3(-0.75,-2.405) 4(-0.25,-2.405) 5(0.25,-2.405) 6(0.75,-2.405) 7(1.25,-2.405) 8(1.75,-2.405) 17(1.75,2.405) 18(1.25,2.405) 19(0.75,2.405) 20(0.25,2.405) 21(-0.25,2.405) 22(-0.75,2.405) 23(-1.25,2.405) 24(-1.75,2.405)
  rect 0.7x0.28 smd: 9(2.405,-1.75) 10(2.405,-1.25) 11(2.405,-0.75) 12(2.405,-0.25) 13(2.405,0.25) 14(2.405,0.75) 15(2.405,1.25) 16(2.405,1.75) 25(-2.405,1.75) 26(-2.405,1.25) 27(-2.405,0.75) 28(-2.405,0.25) 29(-2.405,-0.25) 30(-2.405,-0.75) 31(-2.405,-1.25) 32(-2.405,-1.75)
  rect 3.15x3.15 smd: 33(0,0)
QFN10-0_4-1_45X1_85H0_55
  custom 0.051x0.051 smd: 1(-0.534,0.2)
  rect 0.711x0.203 smd: 2(-0.623,-0.2) 6(0.623,-0.2) 7(0.623,0.2)
  rect 0.203x0.711 smd: 3(-0.4,-0.824) 4(0,-0.824) 5(0.4,-0.824) 8(0.4,0.824) 9(0,0.824) 10(-0.4,0.824)
QFN12-0_4-1_8X1_8H0_6-SGM4574
  rect 0.625x0.2 smd: 1(-0.787,0.2)
  rect 0.6x0.2 smd: 2(-0.8,-0.2) 7(0.8,-0.2) 8(0.8,0.2)
  rect 0.2x0.6 smd: 3(-0.6,-0.8) 4(-0.2,-0.8) 5(0.2,-0.8) 6(0.6,-0.8) 9(0.6,0.8) 10(0.2,0.8) 11(-0.2,0.8) 12(-0.6,0.8)
QFN12-0_8-SQ4_0H0_9
  rect 0.7x0.3 smd: 1(-1.85,0.8) 2(-1.85,0) 3(-1.85,-0.8) 7(1.85,-0.8) 8(1.85,0) 9(1.85,0.8)
  rect 0.3x0.7 smd: 4(-0.8,-1.85) 5(0,-1.85) 6(0.8,-1.85) 10(0.8,1.85) 11(0,1.85) 12(-0.8,1.85)
  rect 2.1x2.1 smd: 13(0,0)
QFN12-0_45-2X2H0_6-SY6897A
  rect 0.6x0.2 smd: 1(-0.9,0.225) 2(-0.9,-0.225) 7(0.9,-0.225) 8(0.9,0.225)
  rect 0.2x0.6 smd: 3(-0.675,-0.9) 4(-0.225,-0.9) 5(0.225,-0.9) 6(0.675,-0.9) 9(0.675,0.9) 10(0.225,0.9) 11(-0.225,0.9) 12(-0.675,0.9)
QFN13-0_5-3X3_5H0_8-SGM6613A
  rect 0.7x0.25 smd: 1(-1.6,1) 2(-1.6,0.5) 3(-1.6,0) 4(-1.6,-0.5) 5(-1.6,-1) 9(1.6,-1) 10(1.6,-0.5) 11(1.6,0) 12(1.6,0.5) 13(1.6,1)
  rect 0.25x3.4 smd: 6(-0.55,0) 7(0,0) 8(0.55,0)
QFN20-0_5-4X4H0_8
  rect 0.8x0.3 smd: 1(-1.765,1) 2(-1.765,0.5) 3(-1.765,0) 4(-1.765,-0.5) 5(-1.765,-1) 11(1.765,-1) 12(1.765,-0.5) 13(1.765,0) 14(1.765,0.5) 15(1.765,1)
  rect 0.3x0.8 smd: 6(-1,-1.765) 7(-0.5,-1.765) 8(0,-1.765) 9(0.5,-1.765) 10(1,-1.765) 16(1,1.765) 17(0.5,1.765) 18(0,1.765) 19(-0.5,1.765) 20(-1,1.765)
  rect 2.1x2.1 smd: 21(0,0)
QFN24-0_5-4X4H0_8-TLV320ADC3140
  rect 0.6x0.25 smd: 1(-1.9,1.25) 2(-1.9,0.75) 3(-1.9,0.25) 4(-1.9,-0.25) 5(-1.9,-0.75) 6(-1.9,-1.25) 13(1.9,-1.25) 14(1.9,-0.75) 15(1.9,-0.25) 16(1.9,0.25) 17(1.9,0.75) 18(1.9,1.25)
  rect 0.25x0.6 smd: 7(-1.25,-1.9) 8(-0.75,-1.9) 9(-0.25,-1.9) 10(0.25,-1.9) 11(0.75,-1.9) 12(1.25,-1.9) 19(1.25,1.9) 20(0.75,1.9) 21(0.25,1.9) 22(-0.25,1.9) 23(-0.75,1.9) 24(-1.25,1.9)
  rect 2.7x2.7 smd: 25(0,0)
QFN28-0_5-5X5H0_8
  oval 0.254x0.7 smd: 1(-1.5,-2.4) 2(-1,-2.4) 3(-0.5,-2.4) 4(0,-2.4) 5(0.5,-2.4) 6(1,-2.4) 7(1.5,-2.4) 15(1.5,2.4) 16(1,2.4) 17(0.5,2.4) 18(0,2.4) 19(-0.5,2.4) 20(-1,2.4) 21(-1.5,2.4)
  oval 0.7x0.254 smd: 8(2.4,-1.5) 9(2.4,-1) 10(2.4,-0.5) 11(2.4,0) 12(2.4,0.5) 13(2.4,1) 14(2.4,1.5) 22(-2.4,1.5) 23(-2.4,1) 24(-2.4,0.5) 25(-2.4,0) 26(-2.4,-0.5) 27(-2.4,-1) 28(-2.4,-1.5)
  rect 3.65x3.65 smd: 29(0,0)
QFN32-0_4-4X4H0_9-RTL8111H
  custom 0.05x0.05 smd: 1(-1.9,1.4) 8(-1.9,-1.4) 9(-1.4,-1.9) 16(1.4,-1.9) 17(1.9,-1.4) 24(1.9,1.4) 25(1.4,1.9) 32(-1.4,1.9)
  rect 0.6x0.2 smd: 2(-1.9,1) 3(-1.9,0.6) 4(-1.9,0.2) 5(-1.9,-0.2) 6(-1.9,-0.6) 7(-1.9,-1) 18(1.9,-1) 19(1.9,-0.6) 20(1.9,-0.2) 21(1.9,0.2) 22(1.9,0.6) 23(1.9,1)
  rect 0.2x0.6 smd: 10(-1,-1.9) 11(-0.6,-1.9) 12(-0.2,-1.9) 13(0.2,-1.9) 14(0.6,-1.9) 15(1,-1.9) 26(1,1.9) 27(0.6,1.9) 28(0.2,1.9) 29(-0.2,1.9) 30(-0.6,1.9) 31(-1,1.9)
  rect 2.7x2.7 smd: 33(0,0)
QFN40-0_5-6X6H0_8-LM5143
  rect 0.6x0.25 smd: 1(-2.9,2.25) 2(-2.9,1.75) 3(-2.9,1.25) 4(-2.9,0.75) 5(-2.9,0.25) 6(-2.9,-0.25) 7(-2.9,-0.75) 8(-2.9,-1.25) 9(-2.9,-1.75) 10(-2.9,-2.25) 21(2.9,-2.25) 22(2.9,-1.75) 23(2.9,-1.25) 24(2.9,-0.75) 25(2.9,-0.25) 26(2.9,0.25) 27(2.9,0.75) 28(2.9,1.25) 29(2.9,1.75) 30(2.9,2.25)
  rect 0.25x0.6 smd: 11(-2.25,-2.9) 12(-1.75,-2.9) 13(-1.25,-2.9) 14(-0.75,-2.9) 15(-0.25,-2.9) 16(0.25,-2.9) 17(0.75,-2.9) 18(1.25,-2.9) 19(1.75,-2.9) 20(2.25,-2.9) 31(2.25,2.9) 32(1.75,2.9) 33(1.25,2.9) 34(0.75,2.9) 35(0.25,2.9) 36(-0.25,2.9) 37(-0.75,2.9) 38(-1.25,2.9) 39(-1.75,2.9) 40(-2.25,2.9)
  rect 3.3x3.3 smd: 41(0,0)
QFN48-0_4-SQ6_0H1_0
  rect 0.6x0.2 smd: 1(-2.9,2.2) 2(-2.9,1.8) 3(-2.9,1.4) 4(-2.9,1) 5(-2.9,0.6) 6(-2.9,0.2) 7(-2.9,-0.2) 8(-2.9,-0.6) 9(-2.9,-1) 10(-2.9,-1.4) 11(-2.9,-1.8) 12(-2.9,-2.2) 25(2.9,-2.2) 26(2.9,-1.8) 27(2.9,-1.4) 28(2.9,-1) 29(2.9,-0.6) 30(2.9,-0.2) 31(2.9,0.2) 32(2.9,0.6) 33(2.9,1) 34(2.9,1.4) 35(2.9,1.8) 36(2.9,2.2)
  rect 0.2x0.6 smd: 13(-2.2,-2.9) 14(-1.8,-2.9) 15(-1.4,-2.9) 16(-1,-2.9) 17(-0.6,-2.9) 18(-0.2,-2.9) 19(0.2,-2.9) 20(0.6,-2.9) 21(1,-2.9) 22(1.4,-2.9) 23(1.8,-2.9) 24(2.2,-2.9) 37(2.2,2.9) 38(1.8,2.9) 39(1.4,2.9) 40(1,2.9) 41(0.6,2.9) 42(0.2,2.9) 43(-0.2,2.9) 44(-0.6,2.9) 45(-1,2.9) 46(-1.4,2.9) 47(-1.8,2.9) 48(-2.2,2.9)
  rect 4.6x4.6 smd: 49(0,0)
QFN56-0_4-7X7H0_9-IT6563
  rect 0.6x0.2 smd: 1(-3.4,2.6) 2(-3.4,2.2) 3(-3.4,1.8) 4(-3.4,1.4) 5(-3.4,1) 6(-3.4,0.6) 7(-3.4,0.2) 8(-3.4,-0.2) 9(-3.4,-0.6) 10(-3.4,-1) 11(-3.4,-1.4) 12(-3.4,-1.8) 13(-3.4,-2.2) 14(-3.4,-2.6) 29(3.4,-2.6) 30(3.4,-2.2) 31(3.4,-1.8) 32(3.4,-1.4) 33(3.4,-1) 34(3.4,-0.6) 35(3.4,-0.2) 36(3.4,0.2) 37(3.4,0.6) 38(3.4,1) 39(3.4,1.4) 40(3.4,1.8) 41(3.4,2.2) 42(3.4,2.6)
  rect 0.2x0.6 smd: 15(-2.6,-3.4) 16(-2.2,-3.4) 17(-1.8,-3.4) 18(-1.4,-3.4) 19(-1,-3.4) 20(-0.6,-3.4) 21(-0.2,-3.4) 22(0.2,-3.4) 23(0.6,-3.4) 24(1,-3.4) 25(1.4,-3.4) 26(1.8,-3.4) 27(2.2,-3.4) 28(2.6,-3.4) 43(2.6,3.4) 44(2.2,3.4) 45(1.8,3.4) 46(1.4,3.4) 47(1,3.4) 48(0.6,3.4) 49(0.2,3.4) 50(-0.2,3.4) 51(-0.6,3.4) 52(-1,3.4) 53(-1.4,3.4) 54(-1.8,3.4) 55(-2.2,3.4) 56(-2.6,3.4)
  custom 1.3x1.3 smd: 57(0,0)
QFN64-0_5-9X9H0_8-MAX96712
  rect 0.6x0.25 smd: 1(-4.4,3.75) 2(-4.4,3.25) 3(-4.4,2.75) 4(-4.4,2.25) 5(-4.4,1.75) 6(-4.4,1.25) 7(-4.4,0.75) 8(-4.4,0.25) 9(-4.4,-0.25) 10(-4.4,-0.75) 11(-4.4,-1.25) 12(-4.4,-1.75) 13(-4.4,-2.25) 14(-4.4,-2.75) 15(-4.4,-3.25) 16(-4.4,-3.75) 33(4.4,-3.75) 34(4.4,-3.25) 35(4.4,-2.75) 36(4.4,-2.25) 37(4.4,-1.75) 38(4.4,-1.25) 39(4.4,-0.75) 40(4.4,-0.25) 41(4.4,0.25) 42(4.4,0.75) 43(4.4,1.25) 44(4.4,1.75) 45(4.4,2.25) 46(4.4,2.75) 47(4.4,3.25) 48(4.4,3.75)
  rect 0.25x0.6 smd: 17(-3.75,-4.4) 18(-3.25,-4.4) 19(-2.75,-4.4) 20(-2.25,-4.4) 21(-1.75,-4.4) 22(-1.25,-4.4) 23(-0.75,-4.4) 24(-0.25,-4.4) 25(0.25,-4.4) 26(0.75,-4.4) 27(1.25,-4.4) 28(1.75,-4.4) 29(2.25,-4.4) 30(2.75,-4.4) 31(3.25,-4.4) 32(3.75,-4.4) 49(3.75,4.4) 50(3.25,4.4) 51(2.75,4.4) 52(2.25,4.4) 53(1.75,4.4) 54(1.25,4.4) 55(0.75,4.4) 56(0.25,4.4) 57(-0.25,4.4) 58(-0.75,4.4) 59(-1.25,4.4) 60(-1.75,4.4) 61(-2.25,4.4) 62(-2.75,4.4) 63(-3.25,4.4) 64(-3.75,4.4)
  rect 6.2x6.2 smd: 65(0,0)
QFN76-0_4-9X9H0_9-VL822-Q7
  rect 0.6x0.2 smd: 1(-4.4,3.6) 2(-4.4,3.2) 3(-4.4,2.8) 4(-4.4,2.4) 5(-4.4,2) 6(-4.4,1.6) 7(-4.4,1.2) 8(-4.4,0.8) 9(-4.4,0.4) 10(-4.4,0) 11(-4.4,-0.4) 12(-4.4,-0.8) 13(-4.4,-1.2) 14(-4.4,-1.6) 15(-4.4,-2) 16(-4.4,-2.4) 17(-4.4,-2.8) 18(-4.4,-3.2) 19(-4.4,-3.6) 39(4.4,-3.6) 40(4.4,-3.2) 41(4.4,-2.8) 42(4.4,-2.4) 43(4.4,-2) 44(4.4,-1.6) 45(4.4,-1.2) 46(4.4,-0.8) 47(4.4,-0.4) 48(4.4,0) 49(4.4,0.4) 50(4.4,0.8) 51(4.4,1.2) 52(4.4,1.6) 53(4.4,2) 54(4.4,2.4) 55(4.4,2.8) 56(4.4,3.2) 57(4.4,3.6)
  rect 0.2x0.6 smd: 20(-3.6,-4.4) 21(-3.2,-4.4) 22(-2.8,-4.4) 23(-2.4,-4.4) 24(-2,-4.4) 25(-1.6,-4.4) 26(-1.2,-4.4) 27(-0.8,-4.4) 28(-0.4,-4.4) 29(0,-4.4) 30(0.4,-4.4) 31(0.8,-4.4) 32(1.2,-4.4) 33(1.6,-4.4) 34(2,-4.4) 35(2.4,-4.4) 36(2.8,-4.4) 37(3.2,-4.4) 38(3.6,-4.4) 58(3.6,4.4) 59(3.2,4.4) 60(2.8,4.4) 61(2.4,4.4) 62(2,4.4) 63(1.6,4.4) 64(1.2,4.4) 65(0.8,4.4) 66(0.4,4.4) 67(0,4.4) 68(-0.4,4.4) 69(-0.8,4.4) 70(-1.2,4.4) 71(-1.6,4.4) 72(-2,4.4) 73(-2.4,4.4) 74(-2.8,4.4) 75(-3.2,4.4) 76(-3.6,4.4)
  rect 6.3x6.3 smd: 77(0,0)
QFP128-0_4-14X14H1_6-RTL8367S
  rect 1.2x0.2 smd: 1(-7.8,6.2) 2(-7.8,5.8) 3(-7.8,5.4) 4(-7.8,5) 5(-7.8,4.6) 6(-7.8,4.2) 7(-7.8,3.8) 8(-7.8,3.4) 9(-7.8,3) 10(-7.8,2.6) 11(-7.8,2.2) 12(-7.8,1.8) 13(-7.8,1.4) 14(-7.8,1) 15(-7.8,0.6) 16(-7.8,0.2) 17(-7.8,-0.2) 18(-7.8,-0.6) 19(-7.8,-1) 20(-7.8,-1.4) 21(-7.8,-1.8) 22(-7.8,-2.2) 23(-7.8,-2.6) 24(-7.8,-3) 25(-7.8,-3.4) 26(-7.8,-3.8) 27(-7.8,-4.2) 28(-7.8,-4.6) 29(-7.8,-5) 30(-7.8,-5.4) 31(-7.8,-5.8) 32(-7.8,-6.2) 65(7.8,-6.2) 66(7.8,-5.8) 67(7.8,-5.4) 68(7.8,-5) 69(7.8,-4.6) 70(7.8,-4.2) 71(7.8,-3.8) 72(7.8,-3.4) 73(7.8,-3) 74(7.8,-2.6) 75(7.8,-2.2) 76(7.8,-1.8) 77(7.8,-1.4) 78(7.8,-1) 79(7.8,-0.6) 80(7.8,-0.2) 81(7.8,0.2) 82(7.8,0.6) 83(7.8,1) 84(7.8,1.4) 85(7.8,1.8) 86(7.8,2.2) 87(7.8,2.6) 88(7.8,3) 89(7.8,3.4) 90(7.8,3.8) 91(7.8,4.2) 92(7.8,4.6) 93(7.8,5) 94(7.8,5.4) 95(7.8,5.8) 96(7.8,6.2)
  rect 0.2x1.2 smd: 33(-6.2,-7.8) 34(-5.8,-7.8) 35(-5.4,-7.8) 36(-5,-7.8) 37(-4.6,-7.8) 38(-4.2,-7.8) 39(-3.8,-7.8) 40(-3.4,-7.8) 41(-3,-7.8) 42(-2.6,-7.8) 43(-2.2,-7.8) 44(-1.8,-7.8) 45(-1.4,-7.8) 46(-1,-7.8) 47(-0.6,-7.8) 48(-0.2,-7.8) 49(0.2,-7.8) 50(0.6,-7.8) 51(1,-7.8) 52(1.4,-7.8) 53(1.8,-7.8) 54(2.2,-7.8) 55(2.6,-7.8) 56(3,-7.8) 57(3.4,-7.8) 58(3.8,-7.8) 59(4.2,-7.8) 60(4.6,-7.8) 61(5,-7.8) 62(5.4,-7.8) 63(5.8,-7.8) 64(6.2,-7.8) 97(6.2,7.8) 98(5.8,7.8) 99(5.4,7.8) 100(5,7.8) 101(4.6,7.8) 102(4.2,7.8) 103(3.8,7.8) 104(3.4,7.8) 105(3,7.8) 106(2.6,7.8) 107(2.2,7.8) 108(1.8,7.8) 109(1.4,7.8) 110(1,7.8) 111(0.6,7.8) 112(0.2,7.8) 113(-0.2,7.8) 114(-0.6,7.8) 115(-1,7.8) 116(-1.4,7.8) 117(-1.8,7.8) 118(-2.2,7.8) 119(-2.6,7.8) 120(-3,7.8) 121(-3.4,7.8) 122(-3.8,7.8) 123(-4.2,7.8) 124(-4.6,7.8) 125(-5,7.8) 126(-5.4,7.8) 127(-5.8,7.8) 128(-6.2,7.8)
R0402
  rect 0.45x0.5 smd: 1(-0.4,0) 2(0.4,0)
RJ45-14P-H13_3-LB2016RJ10P1330-11
  round 3.2 hole 3.2 unplated: (-5.715,0) (5.715,0)
  round 1.5 hole 0.9: 1(-5.715,8.89) 2(-4.445,6.35) 3(-3.175,8.89) 4(-1.905,6.35) 5(-0.635,8.89) 6(0.635,6.35) 7(1.905,8.89) 8(3.175,6.35) 9(4.445,8.89) 10(5.715,6.35)
  round 1.6 hole 1: 11(-6.63,-4.9) 12(-4.09,-4.9) 13(4.09,-4.9) 14(6.63,-4.9)
  round 2.2 hole 1.6: G1(-7.825,3.05) G2(7.825,3.05)
SC70-5H1_1
  rect 0.35x0.7 smd: 1(-0.65,-0.95) 2(0,-0.95) 3(0.65,-0.95) 4(0.65,0.95) 5(-0.65,0.95)
SC70-6-0_65-2X1_25H1_1
  rect 0.35x0.7 smd: 1(-0.65,-0.95) 2(0,-0.95) 3(0.65,-0.95) 4(0.65,0.95) 5(0,0.95) 6(-0.65,0.95)
SC0603
  custom 0.138x0.138 smd: 1(-0.675,0) 2(0.675,0)
SC0603A-H0_9
  rect 0.7x0.9 smd: 1(-0.69,0) 2(0.69,0)
SC0603BC-H1_0
  rect 0.79x1 smd: 1(-0.755,0) 2(0.755,0)
SC0603DE-H1_0
  rect 0.85x1.1 smd: 1(-0.775,0) 2(0.775,0)
SC0603DE-H1_1
  rect 0.85x1.1 smd: 1(-0.775,0) 2(0.775,0)
SC0805
  custom 0.163x0.163 smd: 1(-0.85,0) 2(0.85,0)
SC0805H1_45
  custom 0.163x0.163 smd: 1(-0.85,0) 2(0.85,0)
SC1206
  rect 1.2x1.65 smd: 1(-1.4,0) 2(1.4,0)
SC1206H1_8
  rect 1.2x1.65 smd: 1(-1.4,0) 2(1.4,0)
SC-6_6X6_6H8_0
  rect 3.5x1 smd: 1(2.65,0) 2(-2.65,0)
SC-10_3X10_3H10_5
  rect 4x1.6 smd: 1(4.1,0) 2(-4.1,0)
SL0603-H1_0
  rect 0.79x1 smd: 1(-0.755,0) 2(0.755,0)
SL0805H1_0
  rect 0.8x1.3 smd: 1(-0.85,0) 2(0.85,0)
SL2016-1_85H0_8
  rect 0.7x1.7 smd: 1(-0.7,0) 2(0.7,0)
SL2520-1_7H1_2
  rect 0.9x2.1 smd: 1(-0.85,0) 2(0.85,0)
SL5020-3-5_4X5_1H2
  rect 1.4x2.5 smd: 1(-2.2,0) 2(2.2,0)
SL-4_0X4_0H1_2
  rect 1.6x4 smd: 1(-1.4,0) 2(1.4,0)
SL-7_3X7_3H5_4-TMPV0754SV
  rect 3x3.5 smd: 1(-3,0) 2(3,0)
SL-10_7X10H4_0
  rect 3.2x4.8 smd: 1(-4.75,0) 2(4.75,0)
SL-10_7X10H5_4
  rect 3.8x4.8 smd: 1(-4.95,0) 2(4.95,0)
SL-11_9X11H10_0
  rect 3.4x11 smd: 1(-3.55,0) 2(3.55,0)
SL-SQ16_9H7-TMPC1707HP
  rect 3.15x12.5 smd: 1(-7.675,0) 2(7.675,0)
SO8-1_27-4_9X3_9H1_7-SIT3088
  rect 1.3x0.6 smd: 1(-2.65,1.905) 2(-2.65,0.635) 3(-2.65,-0.635) 4(-2.65,-1.905) 5(2.65,-1.905) 6(2.65,-0.635) 7(2.65,0.635) 8(2.65,1.905)
SOD123H1_4
  rect 0.7x0.7 smd: 1(-1.7,0) 2(1.7,0)
SOIC8-1_27-4_9X6_0H1_75
  rect 1.3x0.6 smd: 1(-2.65,1.905) 2(-2.65,0.635) 3(-2.65,-0.635) 4(-2.65,-1.905) 5(2.65,-1.905) 6(2.65,-0.635) 7(2.65,0.635) 8(2.65,1.905)
SOP24-0_99-15_24X7_62H4_14
  rect 0.65x1.8 smd: 1(-5.448,-4.496) 2(-4.458,-4.496) 3(-3.467,-4.496) 4(-2.477,-4.496) 5(-1.486,-4.496) 6(-0.495,-4.496) 7(0.495,-4.496) 8(1.486,-4.496) 9(2.477,-4.496) 10(3.467,-4.496) 11(4.458,-4.496) 12(5.448,-4.496) 13(5.448,4.496) 14(4.458,4.496) 15(3.467,4.496) 16(2.477,4.496) 17(1.486,4.496) 18(0.495,4.496) 19(-0.495,4.496) 20(-1.486,4.496) 21(-2.477,4.496) 22(-3.467,4.496) 23(-4.458,4.496) 24(-5.448,4.496)
SOT23-5H1_25
  rect 0.6x1 smd: 1(-0.95,-1.2) 2(0,-1.2) 3(0.95,-1.2) 4(0.95,1.2) 5(-0.95,1.2)
SOT23-5H1_45
  rect 0.6x1 smd: 1(-0.95,-1.2) 2(0,-1.2) 3(0.95,-1.2) 4(0.95,1.2) 5(-0.95,1.2)
SOT23-6H1_4
  rect 0.6x1 smd: 1(-0.95,-1.2) 2(0,-1.2) 3(0.95,-1.2) 4(0.95,1.2) 5(0,1.2) 6(-0.95,1.2)
SOT23-8H1_45
  rect 0.4x1 smd: 1(-0.975,-1.2) 2(-0.325,-1.2) 3(0.325,-1.2) 4(0.975,-1.2) 5(0.975,1.2) 6(0.325,1.2) 7(-0.325,1.2) 8(-0.975,1.2)
SOT23-H1_1
  rect 0.5x0.6 smd: 1(-0.95,-1) 2(0.95,-1) 3(0,1)
SOT23H1_1
  rect 0.8x1.1 smd: 1(-0.95,-1.175) 2(0.95,-1.175) 3(0,1.175)
SOT23H1_2
  rect 0.8x0.9 smd: 1(-0.95,-1.075) 2(0.95,-1.075) 3(0,1.075)
SP2-L1
  rect 0.15x0.1 smd: 1(0.15,0) 2(-0.13,0)
SP2-L3P
  rect 0.2x0.5 smd: 1(0.18,0) 2(-0.13,0)
SR0805
  custom 0.163x0.163 smd: 1(-0.85,0) 2(0.85,0)
SR1206
  rect 1x1.6 smd: 1(-1.4,0) 2(1.4,0)
SR2512H0_65
  rect 1.5x3.2 smd: 1(-2.75,0) 2(2.75,0)
SW4-H1_5-TSK-051510-160-KJ
  rect 1.5x1 smd: 1(2.95,1.85) 2(-2.95,1.85) 3(2.95,-1.85) 4(-2.95,-1.85)
SW12-H2_3-DS-D1-06-G
  rect 0.76x1.25 smd: 1(-3.175,-3.8) 2(-1.905,-3.8) 3(-0.635,-3.8) 4(0.635,-3.8) 5(1.905,-3.8) 6(3.175,-3.8) 7(3.175,3.8) 8(1.905,3.8) 9(0.635,3.8) 10(-0.635,3.8) 11(-1.905,3.8) 12(-3.175,3.8)
TP0_5
  round 0.5 smd: 1(0,0)
TP0_8
  round 0.8 smd: 1(0,0)
TP1_0
  round 1 smd: 1(0,0)
TP2_0
  round 2 smd: 1(0,0)
TSSOP16-0_65-5X4_4H1_2
  rect 1.2x0.35 smd: 1(-2.9,2.275) 2(-2.9,1.625) 3(-2.9,0.975) 4(-2.9,0.325) 5(-2.9,-0.325) 6(-2.9,-0.975) 7(-2.9,-1.625) 8(-2.9,-2.275) 9(2.9,-2.275) 10(2.9,-1.625) 11(2.9,-0.975) 12(2.9,-0.325) 13(2.9,0.325) 14(2.9,0.975) 15(2.9,1.625) 16(2.9,2.275)
TSSOP28-0_65-9_7X4_4H1_2-TAS5805M
  rect 1.2x0.35 smd: 1(-2.9,4.225) 2(-2.9,3.575) 3(-2.9,2.925) 4(-2.9,2.275) 5(-2.9,1.625) 6(-2.9,0.975) 7(-2.9,0.325) 8(-2.9,-0.325) 9(-2.9,-0.975) 10(-2.9,-1.625) 11(-2.9,-2.275) 12(-2.9,-2.925) 13(-2.9,-3.575) 14(-2.9,-4.225) 15(2.9,-4.225) 16(2.9,-3.575) 17(2.9,-2.925) 18(2.9,-2.275) 19(2.9,-1.625) 20(2.9,-0.975) 21(2.9,-0.325) 22(2.9,0.325) 23(2.9,0.975) 24(2.9,1.625) 25(2.9,2.275) 26(2.9,2.925) 27(2.9,3.575) 28(2.9,4.225)
  rect 3.1x4.05 smd: 29(0,0)
TSSOP38-0_5-9_8X4_5H1_2
  rect 0.3x1.5 smd: 1(-4.5,-2.9) 2(-4,-2.9) 3(-3.5,-2.9) 4(-3,-2.9) 5(-2.5,-2.9) 6(-2,-2.9) 7(-1.5,-2.9) 8(-1,-2.9) 9(-0.5,-2.9) 10(0,-2.9) 11(0.5,-2.9) 12(1,-2.9) 13(1.5,-2.9) 14(2,-2.9) 15(2.5,-2.9) 16(3,-2.9) 17(3.5,-2.9) 18(4,-2.9) 19(4.5,-2.9) 20(4.5,2.9) 21(4,2.9) 22(3.5,2.9) 23(3,2.9) 24(2.5,2.9) 25(2,2.9) 26(1.5,2.9) 27(1,2.9) 28(0.5,2.9) 29(0,2.9) 30(-0.5,2.9) 31(-1,2.9) 32(-1.5,2.9) 33(-2,2.9) 34(-2.5,2.9) 35(-3,2.9) 36(-3.5,2.9) 37(-4,2.9) 38(-4.5,2.9)
  rect 4.7x2.9 smd: 39(0,0)
unnamed
  round 1.7 hole 1.7 unplated: (0,0)
USON8-0_5-3_0X2_0H0_55
  rect 0.55x0.3 smd: 1(-1.225,0.75) 2(-1.225,0.25) 3(-1.225,-0.25) 4(-1.225,-0.75) 5(1.225,-0.75) 6(1.225,-0.25) 7(1.225,0.25) 8(1.225,0.75)
  rect 0.25x1.6 smd: 9(0,0)
USOP8-0_65-H1_1-DS1308
  rect 1.35x0.4 smd: 1(-2.15,0.975) 2(-2.15,0.325) 3(-2.15,-0.325) 4(-2.15,-0.975) 5(2.15,-0.975) 6(2.15,-0.325) 7(2.15,0.325) 8(2.15,0.975)
VDFN14-0_65-4_5X3H0_9
  rect 0.35x0.85 smd: 1(-1.95,-1.5) 2(-1.3,-1.5) 3(-0.65,-1.5) 4(0,-1.5) 5(0.65,-1.5) 6(1.3,-1.5) 7(1.95,-1.5) 8(1.95,1.5) 9(1.3,1.5) 10(0.65,1.5) 11(0,1.5) 12(-0.65,1.5) 13(-1.3,1.5) 14(-1.95,1.5)
  rect 4.25x1.65 smd: 15(0,0)
VSSOP10-0_5-3X5H1_1-IM5060
  rect 1.45x0.3 smd: 1(-2.2,1) 2(-2.2,0.5) 3(-2.2,0) 4(-2.2,-0.5) 5(-2.2,-1) 6(2.2,-1) 7(2.2,-0.5) 8(2.2,0) 9(2.2,0.5) 10(2.2,1)
WTB2S-2H5_7-SM03B-PASS-TB
  oval 1.8x0.8 hole 1.8x0.8 unplated: (-3.2,-3.25)
  round 0.9 hole 0.9 unplated: (3.2,-3.25)
  rect 1x2.7 smd: 1(1,-4.55) 2(-1,-4.55)
  rect 1.8x3.8 smd: G1(3.35,0) G2(-3.35,0)
WTB2U-1_25H5_7-53398
  rect 0.8x1.3 smd: 1(-0.625,0) 2(0.625,0)
  rect 2.1x3 smd: G1(-3.175,-2.75) G2(3.175,-2.75)
WTB3U-1_25H5_7-53398
  rect 0.8x1.3 smd: 1(-0.625,0) 2(0.625,0) 3(1.875,0)
  rect 2.1x3 smd: G1(-3.175,-2.75) G2(4.425,-2.75)
WTB5U-1_25H5_7-53398
  rect 0.8x1.3 smd: 1(-2.5,0) 2(-1.25,0) 3(0,0) 4(1.25,0) 5(2.5,0)
  rect 2.1x3 smd: G1(-5.05,-2.75) G2(5.05,-2.75)
WTB6U-1_25H5_7-53398
  rect 0.8x1.3 smd: 1(-3.125,0) 2(-1.875,0) 3(-0.625,0) 4(0.625,0) 5(1.875,0) 6(3.125,0)
  rect 2.1x3 smd: G1(-5.675,-2.75) G2(5.675,-2.75)

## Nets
